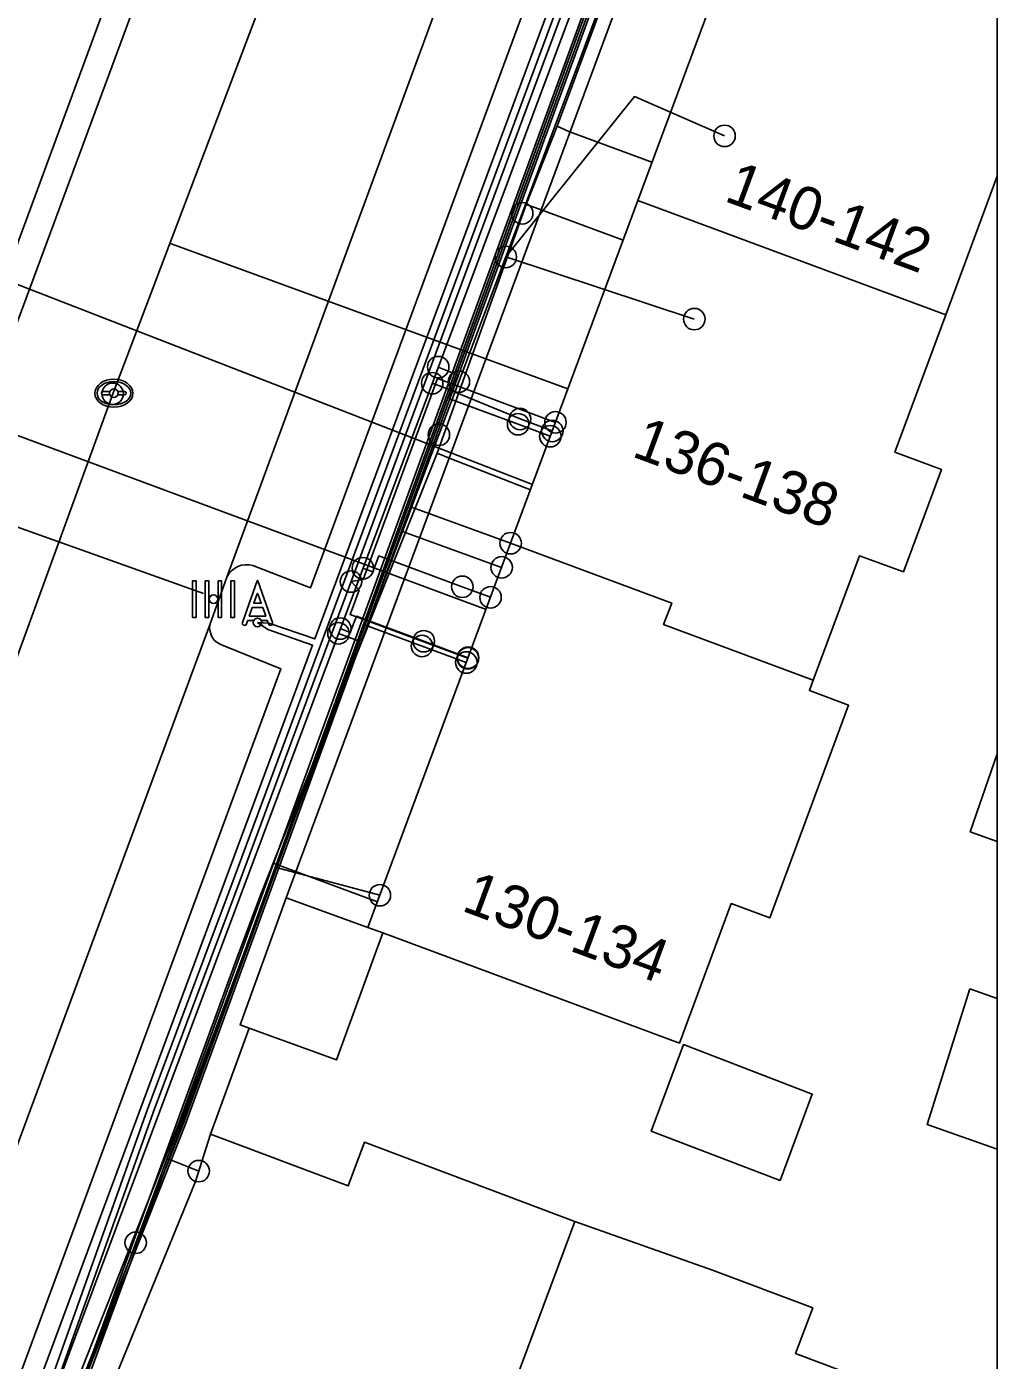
# Model space of a CAD drawing. Extents: x 192672 to 192910, y 446344 to 446512.
# Drawn here: x 192838.05 to 192860.64, y 446383.03 to 446414.08 of the extents above; entities that cross this region are included whole.
import ezdxf

# ---------------------------------------------------------------- set-up
doc = ezdxf.new("R2010")
doc.units = 0
for name, color, linetype in [('1010 viewport', 7, 'Continuous'), ('B-OI-KL-()_OVERIG_RIOOLVRIJVERVAL-S', 7, 'Continuous'), ('B-OI-KL-BUISLEIDING_OLIEGASCHEMICALIEN_GASLAGEDRUK-G', 7, 'Continuous'), ('B-OI-KL-DATA-G', 7, 'Continuous'), ('B-OI-KL-DATA_GTWP-S', 7, 'Continuous'), ('B-OI-KL-DATA_KABELBED-G', 7, 'Continuous'), ('B-OI-KL-DATA_MOF-S', 7, 'Continuous'), ('B-OI-KL-ET_LS-G', 7, 'Continuous'), ('B-OI-KL-ET_LS_DELIVERYPOINT-S', 7, 'Continuous'), ('B-OI-KL-ET_LS_MOF-S', 7, 'Continuous'), ('B-OI-KL-ET_MS-G', 7, 'Continuous'), ('B-OI-KL-GAS_LD_AFTAKZADEL-S', 7, 'Continuous'), ('B-OI-KL-GAS_LD_DELIVERYPOINT-S', 7, 'Continuous'), ('B-OI-KL-GAS_LD_OVERGANGSSTUK-S', 7, 'Continuous'), ('B-OI-KL-WATER-G', 7, 'Continuous'), ('B-OI-RI-RIOOLVRIJVERVAL-G', 7, 'Continuous'), ('bovenleidingmast', 7, 'Continuous'), ('Default', 7, 'Continuous'), ('huisnummerreeks BGT', 7, 'Continuous'), ('inspectie-   rioolput', 7, 'Continuous'), ('kant open verharding', 7, 'Continuous'), ('kant verharding', 7, 'Continuous'), ('kolk', 7, 'Continuous'), ('pand op maaiveld vlak', 7, 'Continuous')]:
    doc.layers.add(name, color=color, linetype=linetype)

# ---------------------------------------------------------------- blocks, each defined once
blk = doc.blocks.new('B-OI-KL-GAS_LD_AFTAKZADEL-S')
at = {"layer": 'Default'}
blk.add_circle((0, 0), 0.25, dxfattribs=at)
blk = doc.blocks.new('B-OI-KL-GAS_LD_DELIVERYPOINT-S')
at = {"layer": 'Default'}
blk.add_circle((0, 0), 0.25, dxfattribs=at)
blk = doc.blocks.new('B-OI-KL-GAS_LD_OVERGANGSSTUK-S')
at = {"layer": 'Default'}
blk.add_circle((0, 0), 0.25, dxfattribs=at)
blk = doc.blocks.new('B-OI-KL-ET_LS_DELIVERYPOINT-S')
at = {"layer": 'Default'}
blk.add_circle((0, 0), 0.25, dxfattribs=at)
blk = doc.blocks.new('B-OI-KL-ET_LS_MOF-S')
at = {"layer": 'Default'}
blk.add_circle((0, 0), 0.25, dxfattribs=at)
blk = doc.blocks.new('B-OI-KL-()_OVERIG_RIOOLVRIJVERVAL-S')
at = {"layer": 'Default'}
blk.add_circle((0, 0), 0.25, dxfattribs=at)
blk = doc.blocks.new('B-OI-KL-DATA_GTWP-S')
at = {"layer": 'Default'}
blk.add_circle((0, 0), 0.25, dxfattribs=at)
blk = doc.blocks.new('B-OI-KL-DATA_MOF-S')
at = {"layer": 'Default'}
blk.add_circle((0, 0), 0.25, dxfattribs=at)

msp = doc.modelspace()

# ---------------------------------------------------------------- linework, layer by layer
at = {"layer": '1010 viewport'}
msp.add_lwpolyline([(192675.743, 446509.756), (192860.643, 446509.756), (192860.643, 446345.556), (192675.743, 446345.556)], close=True, dxfattribs=at)
at = {"layer": 'B-OI-KL-BUISLEIDING_OLIEGASCHEMICALIEN_GASLAGEDRUK-G'}
for points in [[(192860.643, 446440.908), (192837.291, 446378.546), (192836.701, 446376.951)], [(192847.628, 446406.15), (192848.092, 446405.963), (192847.887, 446405.414), (192849.488, 446404.82)], [(192847.488, 446405.775), (192847.722, 446405.688), (192849.533, 446404.942)], [(192849.533, 446404.942), (192850.283, 446404.663)], [(192849.488, 446404.82), (192850.237, 446404.541)], [(192845.874, 446401.468), (192846.109, 446401.38), (192846.249, 446401.755), (192848.189, 446401.035)], [(192848.189, 446401.035), (192848.846, 446400.791)], [(192845.348, 446400.063), (192845.582, 446399.975), (192845.723, 446400.351), (192847.292, 446399.768)], [(192845.306, 446399.951), (192845.774, 446399.775), (192845.915, 446400.151), (192847.251, 446399.656)], [(192847.251, 446399.656), (192848.282, 446399.273)], [(192847.292, 446399.768), (192848.324, 446399.385)]]:
    msp.add_lwpolyline(points, dxfattribs=at)
at = {"layer": 'B-OI-KL-DATA-G'}
for points in [[(192860.643, 446439.84), (192858.649, 446434.44), (192856.346, 446428.22), (192855.817, 446426.808), (192852.769, 446418.173), (192850.395, 446411.758), (192849.678, 446409.935), (192847.607, 446404.149), (192843.783, 446394.6), (192843.506, 446393.897), (192842.911, 446392.302), (192838.563, 446380.393), (192835.548, 446381.218), (192827.915, 446382.904), (192827.409, 446383.075)], [(192852.769, 446418.173), (192850.395, 446411.758)], [(192850.395, 446411.758), (192849.678, 446409.935)], [(192850.395, 446411.758), (192850.669, 446411.636), (192852.603, 446410.918)], [(192849.678, 446409.935), (192847.607, 446404.149)], [(192849.678, 446409.935), (192849.983, 446409.831), (192851.932, 446409.108)], [(192847.607, 446404.149), (192843.783, 446394.6), (192846.213, 446393.699)], [(192847.607, 446404.149), (192847.904, 446404.025), (192849.775, 446403.294)]]:
    msp.add_lwpolyline(points, dxfattribs=at)
at = {"layer": 'B-OI-KL-DATA_KABELBED-G'}
for points in [[(192838.255, 446379.469), (192838.255, 446379.47), (192838.938, 446381.357), (192840.586, 446385.763), (192841.32, 446387.726), (192843.852, 446394.497), (192846.796, 446402.321), (192846.942, 446402.709), (192847.01, 446402.889), (192847.644, 446404.574), (192849.201, 446408.714), (192849.583, 446409.729), (192850.936, 446413.324), (192853.193, 446419.403), (192853.789, 446421.011), (192855.272, 446425.005), (192855.881, 446426.646), (192856.018, 446427.015), (192856.437, 446428.143), (192856.437, 446428.144), (192858.561, 446433.865), (192860.643, 446439.476)], [(192849.201, 446408.714), (192849.201, 446408.714), (192852.197, 446412.448), (192854.294, 446411.534)], [(192849.583, 446409.729), (192849.201, 446408.714), (192849.201, 446408.714), (192847.644, 446404.574), (192847.01, 446402.889), (192846.942, 446402.709), (192846.796, 446402.321), (192849.104, 446401.488)], [(192849.201, 446408.714), (192853.59, 446407.267)], [(192847.644, 446404.574), (192847.01, 446402.889), (192846.942, 446402.709), (192846.796, 446402.321), (192843.852, 446394.497), (192846.271, 446393.854)], [(192847.644, 446404.574), (192847.01, 446402.889), (192849.313, 446402.05)], [(192840.586, 446385.763), (192841.32, 446387.726), (192842.052, 446387.431)]]:
    msp.add_lwpolyline(points, dxfattribs=at)
at = {"layer": 'B-OI-KL-ET_LS-G'}
for points in [[(192860.643, 446441.28), (192860.441, 446440.739), (192854.355, 446425.19), (192842.875, 446394.261), (192840.85, 446388.847), (192837.243, 446378.73), (192835.476, 446373.97), (192827.337, 446352.451)], [(192860.643, 446440.911), (192854.495, 446425.137), (192851.155, 446416.128), (192850.03, 446413.108), (192845.598, 446401.157), (192844.715, 446398.789), (192843.015, 446394.209), (192840.991, 446388.796), (192837.387, 446378.685), (192825.907, 446382.752), (192810.831, 446388.289), (192807.287, 446389.624)], [(192860.643, 446440.424), (192854.87, 446424.998), (192841.598, 446388.562), (192838.758, 446381.37), (192827.735, 446350.8), (192826.469, 446347.4), (192825.842, 446345.716), (192814.875, 446350.065), (192814.484, 446350.219), (192814.326, 446349.794)], [(192860.643, 446440.124), (192852.81, 446419.045), (192841.692, 446388.528), (192838.898, 446381.453), (192837.868, 446378.608), (192831.14, 446359.912), (192827.608, 446350.172), (192825.86, 446345.608), (192823.662, 446346.45), (192813.113, 446350.64), (192812.633, 446349.432), (192812.489, 446349.272), (192812.519, 446349.474), (192812.973, 446350.693), (192815.284, 446357.022), (192818.135, 446364.563), (192821.002, 446371.788), (192821.837, 446373.928), (192823.179, 446377.806), (192823.767, 446377.593)], [(192860.643, 446439.997), (192855.011, 446424.946), (192841.739, 446388.511), (192838.898, 446381.315), (192827.876, 446350.748), (192826.61, 446347.349), (192825.942, 446345.556)], [(192843.422, 446400.204), (192843.684, 446400.19), (192844.752, 446399.82), (192856.51, 446431.49), (192855.51, 446431.864), (192855.318, 446432.016)], [(192845.598, 446401.157), (192845.878, 446401.204), (192847.614, 446405.881), (192850.357, 446404.863)], [(192845.598, 446401.157), (192845.787, 446400.959), (192845.575, 446400.389), (192848.319, 446399.371)], [(192833.908, 446373.996), (192835.164, 446373.55), (192837.21, 446379.066), (192837.068, 446379.116), (192844.704, 446399.678), (192843.658, 446400.042), (192843.422, 446400.204)]]:
    msp.add_lwpolyline(points, dxfattribs=at)
at = {"layer": 'B-OI-KL-ET_MS-G'}
msp.add_lwpolyline([(192825.9, 446345.556), (192827.561, 446350.19), (192831.093, 446359.929), (192841.669, 446388.539), (192852.848, 446419.335), (192860.643, 446440.337)], dxfattribs=at)
at = {"layer": 'B-OI-KL-WATER-G'}
for points in [[(192834.453, 446409.387), (192849.82, 446403.416)], [(192833.298, 446406.243), (192848.741, 446400.51)]]:
    msp.add_lwpolyline(points, dxfattribs=at)
at = {"layer": 'B-OI-RI-RIOOLVRIJVERVAL-G'}
for points in [[(192855.92, 446447.38), (192840.05, 446405.53)], [(192846.181, 446429.773), (192836.26, 446402.977)], [(192850.648, 446405.648), (192841.375, 446409.034)], [(192840.05, 446405.53), (192825.54, 446365.66)], [(192842.163, 446400.883), (192835.944, 446403.095)]]:
    msp.add_lwpolyline(points, dxfattribs=at)
at = {"layer": 'bovenleidingmast'}
for p, q in [((192843.412, 446401.176), (192843.071, 446400.203)), ((192843.771, 446400.203), (192843.43, 446401.176))]:
    msp.add_line(p, q, dxfattribs=at)
for points in [[(192843.43, 446400.873), (192843.508, 446400.653), (192843.334, 446400.653), (192843.412, 446400.873)], [(192843.165, 446400.17), (192843.194, 446400.253), (192843.334, 446400.253)], [(192843.508, 446400.253), (192843.648, 446400.253), (192843.677, 446400.17)]]:
    msp.add_lwpolyline(points, dxfattribs=at)
msp.add_lwpolyline([(192843.543, 446400.553), (192843.613, 446400.353), (192843.229, 446400.353), (192843.299, 446400.553)], close=True, dxfattribs=at)
for centre, radius, start, end in [((192843.421, 446401.173), 0.01, 19.29, 160.71), ((192843.421, 446400.87), 0.01, 19.29, 160.71), ((192843.118, 446400.186), 0.05, 160.71, 340.71), ((192843.421, 446400.203), 0.1, 0, 180), ((192843.421, 446400.203), 0.1, 180, 0), ((192843.421, 446400.203), 0.1, 30, 150), ((192843.724, 446400.186), 0.05, 199.29, 19.29)]:
    msp.add_arc(centre, radius, start, end, dxfattribs=at)
at = {"layer": 'inspectie-   rioolput'}
for p, q in [((192839.984, 446405.579), (192839.827, 446405.579)), ((192839.827, 446405.504), (192839.984, 446405.504)), ((192840.327, 446405.579), (192840.17, 446405.579)), ((192840.17, 446405.504), (192840.327, 446405.504))]:
    msp.add_line(p, q, dxfattribs=at)
for centre, radius, start, end in [((192839.827, 446405.542), 0.0375, 90, 270), ((192840.077, 446405.542), 0.1, 0, 180), ((192840.077, 446405.542), 0.1, 157.9757, 180), ((192840.077, 446405.542), 0.1, 180, 202.0243), ((192840.077, 446405.542), 0.1, 180, 0), ((192840.077, 446405.542), 0.1, 0, 22.0243), ((192840.077, 446405.542), 0.1, 337.9757, 0), ((192840.327, 446405.542), 0.0375, 270, 90)]:
    msp.add_arc(centre, radius, start, end, dxfattribs=at)
for major_axis, ratio in [((-0.442, 0), 0.73911), ((-0.392, 0), 0.689655)]:
    msp.add_ellipse((192840.077, 446405.542), major_axis=major_axis, ratio=ratio, dxfattribs=at)
at = {"layer": 'kant open verharding'}
for p, q in [((192844.09, 446393.794), (192860.643, 446438.476)), ((192842.706, 446401.261), (192842.311, 446400.15)), ((192842.324, 446388.292), (192843.225, 446390.76))]:
    msp.add_line(p, q, dxfattribs=at)
at = {"layer": 'kant verharding'}
for p, q in [((192835.879, 446403.721), (192847.824, 446436.149)), ((192854.067, 446432.141), (192842.706, 446401.261)), ((192842.311, 446400.15), (192835.688, 446382.26))]:
    msp.add_line(p, q, dxfattribs=at)
for points in [[(192854.375, 446431.535), (192855.749, 446431.055), (192844.653, 446401.014), (192843.315, 446401.529)], [(192842.625, 446399.67), (192843.965, 446399.128), (192837.574, 446381.816), (192836.276, 446382.332)]]:
    msp.add_lwpolyline(points, dxfattribs=at)
for centre, radius, start, end in [((192843.168, 446401.037), 0.513, 73.338, 154.1673), ((192842.733, 446400.083), 0.427, 170.9955, 255.3872)]:
    msp.add_arc(centre, radius, start, end, dxfattribs=at)
at = {"layer": 'kolk'}
for points in [[(192841.992, 446400.749), (192841.992, 446401.174), (192841.907, 446401.174), (192841.907, 446400.749), (192841.907, 446400.324), (192841.992, 446400.324)], [(192842.29, 446400.749), (192842.29, 446401.174), (192842.205, 446401.174), (192842.205, 446400.749), (192842.205, 446400.324), (192842.29, 446400.324)], [(192842.587, 446400.749), (192842.587, 446401.174), (192842.502, 446401.174), (192842.502, 446400.749), (192842.502, 446400.324), (192842.587, 446400.324)], [(192842.885, 446400.749), (192842.885, 446401.174), (192842.8, 446401.174), (192842.8, 446400.749), (192842.8, 446400.324), (192842.885, 446400.324)]]:
    msp.add_lwpolyline(points, close=True, dxfattribs=at)
for start, end in [(0, 180), (180, 0)]:
    msp.add_arc((192842.396, 446400.749), 0.1, start, end, dxfattribs=at)
at = {"layer": 'pand op maaiveld vlak'}
for p, q in [((192852.273, 446410.027), (192855.24, 446418.019)), ((192859.445, 446407.365), (192860.643, 446410.593)), ((192852.273, 446410.027), (192849.313, 446402.05)), ((192859.445, 446407.365), (192852.273, 446410.027)), ((192845.992, 446393.104), (192844.09, 446393.794)), ((192845.992, 446393.104), (192846.336, 446392.976)), ((192860.643, 446391.45), (192860.005, 446391.677))]:
    msp.add_line(p, q, dxfattribs=at)
for points in [[(192859.445, 446407.365), (192858.259, 446404.169), (192859.343, 446403.767), (192858.459, 446401.384), (192857.432, 446401.756), (192856.359, 446398.863)], [(192849.313, 446402.05), (192846.032, 446393.211), (192845.992, 446393.104)], [(192849.313, 446402.05), (192853.063, 446400.658), (192852.876, 446400.155), (192856.359, 446398.863)], [(192846.336, 446392.976), (192853.244, 446390.412), (192854.45, 446393.66), (192855.345, 446393.328), (192857.182, 446398.278), (192856.268, 446398.618), (192856.359, 446398.863)], [(192860.643, 446397.15), (192860.015, 446395.329), (192860.643, 446395.104)], [(192844.09, 446393.794), (192843.017, 446390.835), (192843.225, 446390.76)], [(192843.225, 446390.76), (192845.264, 446390.021), (192846.336, 446392.976)], [(192860.005, 446391.677), (192859.009, 446388.515), (192860.643, 446387.944)], [(192855.585, 446387.216), (192856.335, 446389.224), (192853.336, 446390.377), (192852.589, 446388.364), (192855.585, 446387.216)], [(192839.5, 446381.146), (192841.977, 446387.192), (192842.324, 446388.292)], [(192842.324, 446388.292), (192845.528, 446387.086), (192845.911, 446388.102), (192850.786, 446386.266), (192850.812, 446386.257)], [(192848.204, 446377.869), (192849.612, 446381.625), (192849.144, 446381.801), (192850.438, 446385.257), (192850.812, 446386.257)], [(192858.994, 446382.037), (192855.947, 446383.185), (192856.346, 446384.245), (192854.014, 446385.124), (192850.812, 446386.257)]]:
    msp.add_lwpolyline(points, dxfattribs=at)

# ---------------------------------------------------------------- block references
at = {"layer": 'B-OI-KL-()_OVERIG_RIOOLVRIJVERVAL-S'}
msp.add_blockref('B-OI-KL-()_OVERIG_RIOOLVRIJVERVAL-S', (192840.05, 446405.53), dxfattribs=at)
at = {"layer": 'B-OI-KL-DATA_GTWP-S'}
for p in [(192854.294, 446411.534), (192849.583, 446409.729), (192849.201, 446408.714), (192849.201, 446408.714), (192853.59, 446407.267), (192847.644, 446404.574), (192847.644, 446404.574), (192849.313, 446402.05), (192849.104, 446401.488), (192846.271, 446393.854), (192842.052, 446387.431), (192840.586, 446385.763)]:
    msp.add_blockref('B-OI-KL-DATA_GTWP-S', p, dxfattribs=at)
at = {"layer": 'B-OI-KL-DATA_MOF-S'}
for p in [(192849.583, 446409.729), (192849.201, 446408.714), (192848.11, 446405.812), (192847.644, 446404.574), (192840.586, 446385.763)]:
    msp.add_blockref('B-OI-KL-DATA_MOF-S', p, dxfattribs=at)
at = {"layer": 'B-OI-KL-ET_LS_DELIVERYPOINT-S'}
for p in [(192850.357, 446404.863), (192850.357, 446404.863), (192848.319, 446399.371), (192848.319, 446399.371), (192848.319, 446399.371)]:
    msp.add_blockref('B-OI-KL-ET_LS_DELIVERYPOINT-S', p, dxfattribs=at)
at = {"layer": 'B-OI-KL-ET_LS_MOF-S'}
msp.add_blockref('B-OI-KL-ET_LS_MOF-S', (192845.598, 446401.157), dxfattribs=at)
at = {"layer": 'B-OI-KL-GAS_LD_AFTAKZADEL-S'}
for p in [(192847.628, 446406.15), (192847.488, 446405.775), (192845.874, 446401.468), (192845.348, 446400.063), (192845.306, 446399.951)]:
    msp.add_blockref('B-OI-KL-GAS_LD_AFTAKZADEL-S', p, dxfattribs=at)
at = {"layer": 'B-OI-KL-GAS_LD_DELIVERYPOINT-S'}
for p in [(192850.283, 446404.663), (192850.237, 446404.541), (192848.846, 446400.791), (192848.324, 446399.385), (192848.282, 446399.273)]:
    msp.add_blockref('B-OI-KL-GAS_LD_DELIVERYPOINT-S', p, dxfattribs=at)
at = {"layer": 'B-OI-KL-GAS_LD_OVERGANGSSTUK-S'}
for p in [(192849.533, 446404.942), (192849.488, 446404.82), (192848.189, 446401.035), (192847.251, 446399.656), (192847.292, 446399.768)]:
    msp.add_blockref('B-OI-KL-GAS_LD_OVERGANGSSTUK-S', p, dxfattribs=at)

# ---------------------------------------------------------------- texts
at = {"layer": 'huisnummerreeks BGT'}
for s, p in [('140-142', (192854.257, 446410.028)), ('136-138', (192852.104, 446404.08)), ('130-134', (192848.143, 446393.504))]:
    msp.add_text(s, height=1, rotation=339.7, dxfattribs=at).set_placement(p)

doc.saveas('drawing.dxf')
